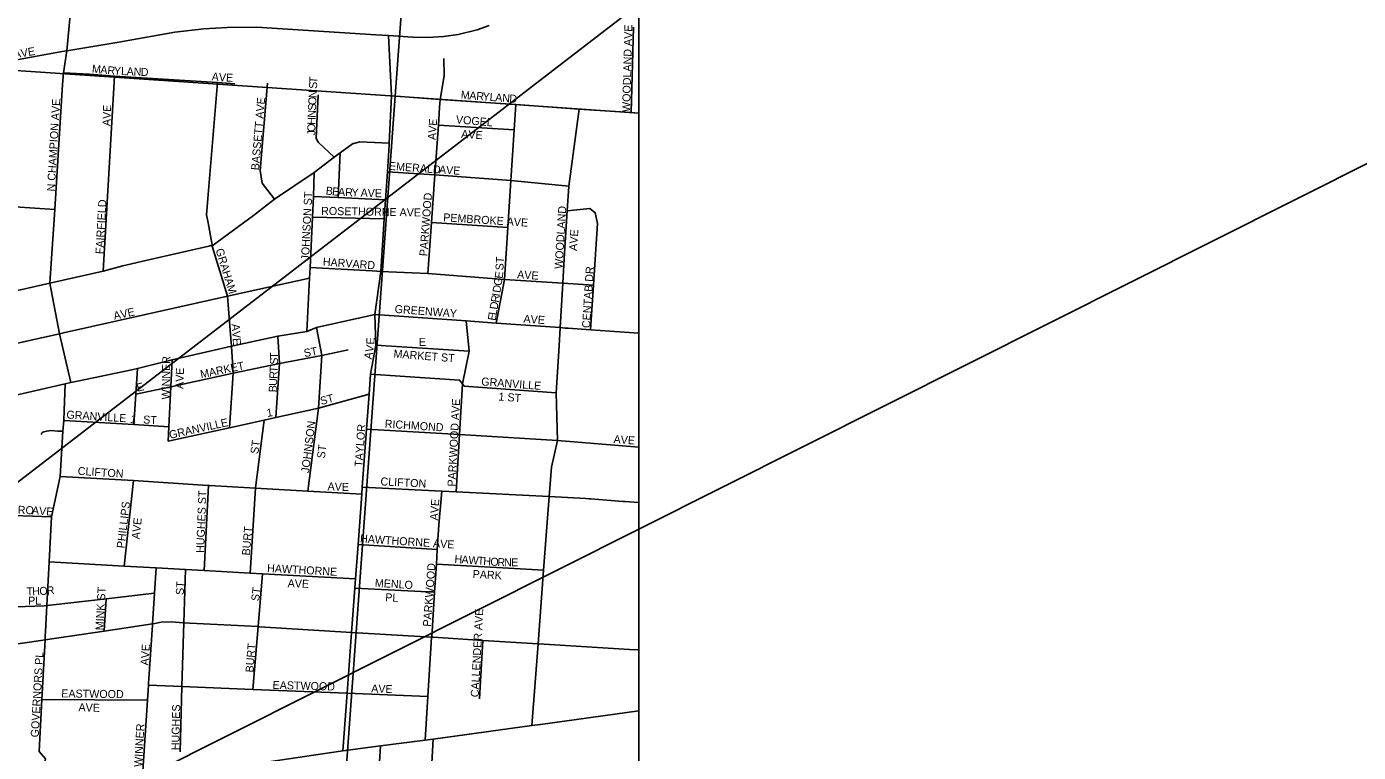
# Model space of a CAD drawing. Extents: x 0 to 34, y -6.2 to 22.
# Drawn here: x 8.351 to 9.927, y 18.357 to 19.216 of the extents above; entities that cross this region are included whole.
import ezdxf

# ---------------------------------------------------------------- set-up
doc = ezdxf.new("R2010")
doc.units = 0
for name, color, linetype in [('GM_X_City_Street', 7, 'Continuous'), ('GM_X_City_Street_Text', 7, 'Continuous'), ('GM_X_Corporation', 7, 'Continuous'), ('GM_X_Section', 7, 'Continuous'), ('GM_X_US_Route', 7, 'Continuous'), ('SH_Data', 7, 'Continuous')]:
    doc.layers.add(name, color=color, linetype=linetype)

msp = doc.modelspace()

# ---------------------------------------------------------------- linework, layer by layer
at = {"layer": 'GM_X_City_Street'}
for points in [[(8.3987, 19.1873), (8.4028, 19.2294), (8.4075, 19.274), (8.4161, 19.3091), (8.445, 19.3931), (8.45, 19.4134), (8.4601, 19.4649), (8.4609, 19.4899), (8.4634, 19.5259)], [(8.393, 19.1863), (8.3987, 19.1873), (8.4604, 19.1976), (8.5267, 19.2092), (8.5608, 19.2131), (8.5883, 19.2147), (8.6233, 19.215), (8.7644, 19.2062)], [(8.7644, 19.2062), (8.7794, 19.2052), (8.808, 19.2033), (8.8254, 19.203), (8.8444, 19.204), (8.8618, 19.2063), (8.8842, 19.2119), (8.8987, 19.2171)], [(9.0664, 19.1141), (9.0693, 19.2152)], [(8.7802, 19.0755), (8.7803, 19.0781), (8.7828, 19.1338), (8.7794, 19.2052)], [(8.3252, 19.174), (8.3329, 19.1755), (8.393, 19.1863)], [(8.3937, 19.1473), (8.3946, 19.1613), (8.3987, 19.1873)], [(8.8398, 19.12), (8.8405, 19.1297), (8.8452, 19.1577), (8.8449, 19.1779)], [(8.3946, 19.1613), (8.4251, 19.1594), (8.455, 19.1571), (8.5769, 19.1496), (8.5976, 19.148)], [(8.4418, 18.9263), (8.455, 19.1571)], [(8.5703, 18.9596), (8.566, 18.9837), (8.564, 18.9932), (8.5657, 19.0125), (8.5769, 19.1496)], [(8.3967, 18.7927), (8.3967, 18.793), (8.4034, 18.7947), (8.3902, 18.8525), (8.3787, 18.9123), (8.3844, 18.9996), (8.3937, 19.1473)], [(8.6445, 19.0118), (8.6299, 19.0305), (8.6276, 19.0457), (8.6362, 19.1488)], [(8.7152, 19.0612), (8.6964, 19.0787), (8.6939, 19.0834), (8.6944, 19.1016), (8.6961, 19.1353)], [(8.7828, 19.1338), (8.8405, 19.1297), (8.9301, 19.1235), (9.005, 19.118), (9.0354, 19.1161)], [(8.8258, 18.9239), (8.8301, 18.9842), (8.8341, 19.0405), (8.8384, 19.0994), (8.8398, 19.12)], [(8.9068, 18.865), (8.9166, 18.9168), (8.9205, 18.978), (8.924, 19.0339), (8.928, 19.0936), (8.9301, 19.1235)], [(8.949, 18.389), (8.9564, 18.4856), (8.963, 18.5728), (8.9697, 18.6597), (8.9724, 18.6947), (8.9792, 18.7261), (8.9779, 18.7826), (8.9814, 18.8383), (8.9826, 18.8597), (8.9857, 18.9124), (8.9874, 18.9415), (8.9909, 18.9979), (8.9928, 19.0271), (9.005, 19.118)], [(9.0354, 19.1161), (9.0664, 19.1141), (9.0755, 19.1135)], [(8.8384, 19.0994), (8.928, 19.0936)], [(8.5766, 18.9609), (8.6197, 18.9924), (8.6445, 19.0118), (8.6916, 19.0434), (8.7152, 19.0612), (8.7221, 19.0663), (8.7369, 19.0772), (8.7456, 19.0796), (8.7803, 19.0781)], [(8.7253, 18.3591), (8.7303, 18.4271), (8.7357, 18.4991), (8.7395, 18.5514), (8.7403, 18.5624), (8.7433, 18.6032), (8.7477, 18.6628), (8.7483, 18.6711), (8.7534, 18.7397), (8.7564, 18.7809), (8.7582, 18.8048), (8.7644, 18.8391), (8.7634, 18.8752), (8.7702, 18.9261), (8.7744, 18.9884), (8.7758, 19.011), (8.7782, 19.0441), (8.7802, 19.0755)], [(8.7199, 19.0136), (8.7221, 19.0663)], [(8.6828, 18.8549), (8.6858, 18.9183), (8.6865, 18.931), (8.6895, 18.9903), (8.6905, 19.0149), (8.6916, 19.0434)], [(8.7782, 19.0441), (8.8341, 19.0405), (8.924, 19.0339), (8.9928, 19.0271)], [(8.6905, 19.0149), (8.7199, 19.0136), (8.7758, 19.011)], [(8.3255, 19.0032), (8.3844, 18.9996)], [(9.0183, 18.8571), (9.0219, 18.9101), (9.0268, 18.9829), (9.0241, 18.9955), (9.0178, 19.0006), (8.9909, 18.9979)], [(8.6895, 18.9903), (8.7744, 18.9884)], [(8.8301, 18.9842), (8.9205, 18.978)], [(8.1258, 18.856), (8.1279, 18.8565), (8.1515, 18.8584), (8.2503, 18.8836), (8.2811, 18.8897), (8.314, 18.8978), (8.3787, 18.9123), (8.4418, 18.9263), (8.4649, 18.9326), (8.4972, 18.9401), (8.5668, 18.9562), (8.5708, 18.9571), (8.5717, 18.9573), (8.5766, 18.9609)], [(8.5933, 18.8417), (8.5887, 18.8968), (8.5709, 18.9562), (8.5708, 18.9571), (8.5706, 18.9581), (8.5703, 18.9596)], [(8.6865, 18.931), (8.7599, 18.9268), (8.7654, 18.9264)], [(8.3949, 18.8535), (8.5887, 18.8968), (8.6858, 18.9183)], [(8.7654, 18.9264), (8.7702, 18.9261), (8.8258, 18.9239), (8.9166, 18.9168), (8.9857, 18.9124), (9.0219, 18.9101)], [(8.4115, 18.7964), (8.4757, 18.8099), (8.4822, 18.8114), (8.5232, 18.8217), (8.5937, 18.8376), (8.5955, 18.838), (8.6484, 18.8497), (8.6828, 18.8549), (8.6943, 18.8599), (8.7634, 18.8752)], [(8.7634, 18.8752), (8.8712, 18.8676), (8.9068, 18.865), (8.9826, 18.8597), (8.9884, 18.8592)], [(8.8594, 18.6654), (8.8633, 18.7331), (8.8669, 18.7933), (8.8748, 18.8317), (8.8712, 18.8676)], [(8.1235, 18.7929), (8.2941, 18.8311), (8.3902, 18.8525), (8.3949, 18.8535)], [(8.6461, 18.7535), (8.6505, 18.8172), (8.6484, 18.8497)], [(8.6839, 18.6663), (8.6966, 18.7645), (8.7003, 18.8267), (8.6943, 18.8599)], [(8.9884, 18.8592), (8.9921, 18.859), (9.0183, 18.8571), (9.0755, 18.8531)], [(8.5914, 18.7413), (8.5954, 18.8056), (8.5937, 18.8376), (8.5935, 18.8386), (8.5933, 18.8417)], [(8.7644, 18.8391), (8.8748, 18.8317)], [(8.4803, 18.781), (8.5217, 18.7897), (8.5954, 18.8056), (8.6505, 18.8172), (8.7003, 18.8267)], [(8.5196, 18.7422), (8.5217, 18.7897), (8.5232, 18.8217)], [(8.7003, 18.8267), (8.7316, 18.8333)], [(8.4781, 18.745), (8.4803, 18.781), (8.4822, 18.8114)], [(8.7582, 18.8048), (8.8635, 18.7976), (8.8669, 18.7933), (8.869, 18.7906), (8.9779, 18.7826)], [(8.3281, 18.7775), (8.3967, 18.793), (8.4034, 18.7947), (8.4115, 18.7964)], [(8.373, 18.4917), (8.3732, 18.4952), (8.3734, 18.5003), (8.3751, 18.5308), (8.3778, 18.5824), (8.3806, 18.6359), (8.3909, 18.6836), (8.3938, 18.737), (8.395, 18.7499), (8.3957, 18.7615), (8.3967, 18.7927)], [(8.5187, 18.7253), (8.5551, 18.7333), (8.5914, 18.7413), (8.6322, 18.7503), (8.6461, 18.7535), (8.6966, 18.7645), (8.7564, 18.7809)], [(8.395, 18.7499), (8.4781, 18.745), (8.5196, 18.7422)], [(8.5187, 18.7253), (8.5196, 18.7422)], [(8.6219, 18.6701), (8.6322, 18.7503)], [(8.7534, 18.7397), (8.8633, 18.7331), (8.9792, 18.7261), (9.0755, 18.7184)], [(8.3683, 18.7333), (8.3697, 18.7355), (8.3715, 18.7365), (8.375, 18.7373), (8.3798, 18.7379), (8.3881, 18.7372), (8.3938, 18.737)], [(8.3909, 18.6836), (8.4775, 18.6787), (8.5654, 18.673), (8.5663, 18.673), (8.5676, 18.6729)], [(8.4665, 18.5775), (8.4775, 18.6787)], [(8.5611, 18.5723), (8.5663, 18.673)], [(8.5676, 18.6729), (8.6218, 18.6698), (8.6839, 18.6663), (8.7477, 18.6628)], [(8.6156, 18.5693), (8.6218, 18.6698), (8.6219, 18.6701)], [(8.7483, 18.6711), (8.8424, 18.6663), (8.8594, 18.6654), (8.9697, 18.6597), (9.013, 18.6575), (9.0169, 18.6572)], [(8.8305, 18.4935), (8.8339, 18.5468), (8.836, 18.5797), (8.8371, 18.5973), (8.8389, 18.6263), (8.8424, 18.6663)], [(9.0169, 18.6572), (9.019, 18.657), (9.0566, 18.6541)], [(9.0566, 18.6541), (9.0589, 18.6539), (9.0755, 18.6526)], [(8.3123, 18.6381), (8.3806, 18.6359)], [(8.7433, 18.6032), (8.8371, 18.5973)], [(8.3778, 18.5824), (8.4665, 18.5775), (8.5043, 18.5754), (8.5392, 18.5735), (8.5611, 18.5723), (8.6156, 18.5693), (8.6303, 18.5685), (8.7403, 18.5624)], [(8.5004, 18.5151), (8.5024, 18.5454), (8.5043, 18.5754)], [(8.5327, 18.3578), (8.535, 18.435), (8.5373, 18.5105), (8.5392, 18.5735)], [(8.6189, 18.4316), (8.6251, 18.5059), (8.6303, 18.5685)], [(8.836, 18.5797), (8.9142, 18.5755), (8.9142, 18.5755)], [(8.9142, 18.5755), (8.963, 18.5728)], [(8.7395, 18.5514), (8.8339, 18.5468)], [(8.3789, 18.5312), (8.4453, 18.5388), (8.5024, 18.5454)], [(8.4428, 18.5007), (8.4453, 18.5388)], [(8.3272, 18.5291), (8.3723, 18.5305), (8.3751, 18.5308), (8.3785, 18.5312), (8.3789, 18.5312)], [(8.3679, 18.4896), (8.3729, 18.4904), (8.4428, 18.5007), (8.5, 18.5091), (8.5007, 18.5092), (8.5102, 18.511), (8.5223, 18.5117), (8.5373, 18.5105), (8.5443, 18.5099), (8.6251, 18.5059), (8.6269, 18.5058), (8.7357, 18.4991), (8.8304, 18.4934), (8.8321, 18.4933), (8.8911, 18.4896), (8.9564, 18.4856), (8.9636, 18.4852), (8.9636, 18.4852)], [(8.4958, 18.4443), (8.4999, 18.5075), (8.5, 18.5091), (8.5004, 18.5151)], [(7.5629, 18.3764), (7.5767, 18.3783), (7.5847, 18.3794), (7.591, 18.3803), (7.5943, 18.3809), (7.6298, 18.3876), (7.6729, 18.3918), (7.749, 18.402), (7.8007, 18.4086), (7.8437, 18.4145), (7.8764, 18.4203), (7.9145, 18.4262), (7.9808, 18.4348), (8.0275, 18.4418), (8.0448, 18.4457), (8.1038, 18.452), (8.1664, 18.4588), (8.2206, 18.4671), (8.289, 18.478), (8.3678, 18.4896), (8.3679, 18.4896)], [(8.3631, 18.3042), (8.3734, 18.3494), (8.3659, 18.3582), (8.3692, 18.4197), (8.3729, 18.4904), (8.373, 18.4917)], [(8.8226, 18.3715), (8.826, 18.4232), (8.8304, 18.4934), (8.8305, 18.4935)], [(8.8869, 18.4203), (8.8911, 18.4896)], [(8.9636, 18.4852), (9.0711, 18.4785), (9.0755, 18.4788)], [(8.4879, 18.3231), (8.4941, 18.4189), (8.4953, 18.4367), (8.4955, 18.4396), (8.4958, 18.4443)], [(8.4953, 18.4367), (8.535, 18.435), (8.6189, 18.4316), (8.7303, 18.4271), (8.826, 18.4232)], [(8.3692, 18.4197), (8.4941, 18.4189)], [(8.7608, 18.2175), (8.7699, 18.3648)], [(8.8262, 18.1321), (8.8232, 18.2118), (8.8321, 18.3727)]]:
    msp.add_lwpolyline(points, dxfattribs=at)
at = {"layer": 'GM_X_Corporation'}
msp.add_lwpolyline([(5.4833, 14.3902), (9.0755, 14.3902), (9.0755, 21.1902), (4.181, 21.1902)], dxfattribs=at)
at = {"layer": 'GM_X_Section'}
for p, q in [((9.0755, 19.1136), (9.0755, 19.6173)), ((9.0755, 18.117), (9.0755, 19.1136))]:
    msp.add_line(p, q, dxfattribs=at)
for points in [[(8.8238, 19.6326), (8.7873, 19.1335), (8.2681, 19.1685), (7.7478, 19.2036), (7.7816, 19.6963)], [(8.2681, 19.1685), (8.7873, 19.1335), (8.7151, 18.1417), (8.198, 18.176)]]:
    msp.add_lwpolyline(points, close=True, dxfattribs=at)
for points in [[(9.0755, 19.6173), (8.9158, 19.6288), (8.8238, 19.6326), (8.7873, 19.1335), (9.0755, 19.1136)], [(9.0755, 19.1136), (8.7873, 19.1335), (8.7151, 18.1417), (9.0755, 18.117)]]:
    msp.add_lwpolyline(points, dxfattribs=at)
at = {"layer": 'GM_X_US_Route'}
for points in [[(8.9591, 18.3903), (9.0755, 18.4061)], [(8.7253, 18.3591), (8.7699, 18.3648), (8.8226, 18.3715), (8.8321, 18.3727), (8.949, 18.389), (8.959, 18.3903), (8.9591, 18.3903)], [(7.7702, 18.2134), (7.8087, 18.22), (7.8159, 18.2211), (7.8223, 18.2222), (7.8858, 18.2297), (7.9034, 18.2324), (7.9636, 18.2412), (8.0195, 18.2496), (8.0627, 18.2556), (8.0929, 18.2603), (8.1544, 18.2697), (8.1656, 18.2711), (8.2163, 18.2789), (8.2815, 18.2885), (8.3569, 18.2998), (8.3631, 18.3042), (8.4344, 18.315), (8.4363, 18.3152), (8.4879, 18.3231), (8.5004, 18.325), (8.5808, 18.3373), (8.6479, 18.3474), (8.7253, 18.3591)]]:
    msp.add_lwpolyline(points, dxfattribs=at)
at = {"layer": 'SH_Data'}
for points in [[(9.0755, 21.1902), (9.0755, 14.3902), (2.2755, 14.3902), (2.2755, 21.1902)], [(10.0459, 19.9888), (6.7517, 17.4551), (10.0459, 19.1081)]]:
    msp.add_lwpolyline(points, close=True, dxfattribs=at)

# ---------------------------------------------------------------- texts
at = {"layer": 'GM_X_City_Street_Text'}
for s, rotation, p in [('WOODLAND AVE', 88.4915, (9.0653, 19.1147)), ('AVE', 10.1268, (8.3368, 19.178)), ('M', 354.6736, (8.4281, 19.1614)), ('A', 354.6809, (8.438, 19.1605)), ('R', 355.0082, (8.4464, 19.1597)), ('Y', 357.0541, (8.4542, 19.159)), ('L', 357.643, (8.4627, 19.1586)), ('A', 357.6509, (8.4693, 19.1583)), ('N', 357.6509, (8.4776, 19.158)), ('D', 357.6509, (8.486, 19.1576)), ('A', 354.4612, (8.5698, 19.1522)), ('V', 356.784, (8.5785, 19.1514)), ('E', 357.126, (8.5869, 19.1509)), ('S', 87.349, (8.6947, 19.142)), ('T', 87.3775, (8.695, 19.1486)), ('N', 87.3548, (8.6942, 19.1311)), ('M', 355.6795, (8.8647, 19.1306)), ('A', 355.6683, (8.8747, 19.1298)), ('R', 355.6637, (8.883, 19.1292)), ('Y', 355.6691, (8.8905, 19.1286)), ('L', 355.6711, (8.8988, 19.128)), ('A', 355.6691, (8.9054, 19.1275)), ('N', 355.6691, (8.9137, 19.1268)), ('D', 355.9615, (8.9221, 19.1262)), ('N CHAMPION AVE', 86.6615, (8.3845, 19.0206)), ('AVE', 88.0261, (8.4503, 19.098)), ('BASSETT AVE', 85.0816, (8.6261, 19.0456)), ('S', 87.349, (8.6935, 19.1162)), ('O', 87.3582, (8.6938, 19.1228)), ('H', 88.1418, (8.6928, 19.0995)), ('N', 87.3984, (8.6931, 19.1078)), ('AVE', 86.0574, (8.8353, 19.0814)), ('VOGEL', 355.1336, (8.8589, 19.1014)), ('O', 89.7814, (8.6928, 19.0913)), ('J', 89.9563, (8.6928, 19.0871)), ('AVE', 356.0569, (8.8652, 19.0843)), ('EMERALD', 355.731, (8.7797, 19.0464)), ('AVE', 356.0569, (8.8389, 19.0422)), ('B', 353.7698, (8.7048, 19.0172)), ('E', 354.3398, (8.7123, 19.0164)), ('A', 357.2457, (8.7195, 19.0157)), ('R', 358.1169, (8.728, 19.0153)), ('Y', 358.1238, (8.7355, 19.015)), ('A', 358.12, (8.7463, 19.0147)), ('V', 358.12, (8.7546, 19.0144)), ('E', 358.1145, (8.763, 19.0141)), ('FAIRFIELD', 86.7772, (8.442, 18.9464)), ('JOHNSON ST', 87.2424, (8.6853, 18.9389)), ('PARKWOOD', 85.7104, (8.8253, 18.9439)), ('ROSETHORNE AVE', 359.0765, (8.6996, 18.9931)), ('PEMBROKE AVE', 356.2915, (8.8439, 18.9856)), ('WOODLAND', 86.51, (8.9853, 18.9289)), ('AVE', 86.0569, (9.0024, 18.9503)), ('GRAHAM', 286.9636, (8.5746, 18.9518)), ('HARVARD', 355.8577, (8.7014, 18.9331)), ('ST', 86.4254, (8.9153, 18.9272)), ('CENTAB DR', 86.3314, (9.0178, 18.8589)), ('G', 80.9103, (8.913, 18.9086)), ('E', 83.0243, (8.9144, 18.9172)), ('AVE', 356.0569, (8.9314, 18.9181)), ('R', 80.5646, (8.9097, 18.8888)), ('I', 80.5714, (8.9109, 18.8962)), ('D', 80.5592, (8.9116, 18.9003)), ('AVE', 12.0958, (8.455, 18.8689)), ('GREENWAY', 355.6563, (8.7864, 18.8772)), ('D', 80.5377, (8.9083, 18.8806)), ('E', 80.5601, (8.9061, 18.8674)), ('L', 80.5584, (8.9072, 18.874)), ('AVE', 356.0569, (8.9389, 18.8656)), ('AVE', 273.8117, (8.5938, 18.8639)), ('ST', 10.6122, (8.6801, 18.8247)), ('V', 80.5919, (8.7611, 18.83)), ('E', 88.0963, (8.7626, 18.8396)), ('E', 0, (8.8154, 18.8381)), ('WINNER', 88.98, (8.5203, 18.7746)), ('MARKET', 11.632, (8.5576, 18.7997)), ('S', 89.1027, (8.6485, 18.8158)), ('T', 89.9457, (8.6486, 18.8227)), ('A', 79.3844, (8.7595, 18.8216)), ('MARKET ST', 355.6037, (8.7851, 18.8243)), ('V', 87.8579, (8.5368, 18.7954)), ('E', 87.8142, (8.5371, 18.8037)), ('R', 87.2372, (8.6477, 18.7989)), ('T', 87.2399, (8.6481, 18.8063)), ('E', 14.0298, (8.4825, 18.7838)), ('A', 88.3384, (8.5366, 18.787)), ('B', 87.2309, (8.647, 18.783)), ('U', 87.2232, (8.6473, 18.7905)), ('GRANVILLE', 355.6565, (8.8889, 18.7914)), ('ST', 14.9378, (8.6999, 18.768)), ('PARKWOOD AVE', 86.9352, (8.8586, 18.6714)), ('1 ST', 355.7579, (8.9093, 18.7735)), ('GRANVILLE', 356.3777, (8.398, 18.7522)), ('1', 350.5377, (8.4732, 18.7472)), ('ST', 356.4262, (8.4888, 18.7464)), ('1', 9.9984, (8.636, 18.7539)), ('GRANVILLE', 12.4488, (8.5209, 18.728)), ('JOHNSON', 82.7636, (8.6853, 18.6873)), ('TAYLOR', 85.9166, (8.7486, 18.6947)), ('RICHMOND', 356.238, (8.7747, 18.7414)), ('ST', 82.8649, (8.6253, 18.7098)), ('AVE', 356.0569, (9.0455, 18.7231)), ('ST', 82.8783, (8.704, 18.7045)), ('CLIFTON', 356.1198, (8.4114, 18.6856)), ('AVE', 358.0186, (8.7071, 18.6672)), ('CLIFTON', 357.087, (8.7697, 18.6731)), ('HUGHES ST', 87.7379, (8.5611, 18.593)), ('METRO', 357.664, (8.3138, 18.6406)), ('AVE', 355.9088, (8.3572, 18.6389)), ('PHILLIPS', 83.2336, (8.467, 18.5982)), ('AVE', 86.0569, (8.8378, 18.6314)), ('AVE', 84.0895, (8.4848, 18.609)), ('BURT', 85.3674, (8.6153, 18.5898)), ('HAWTHORNE AVE', 356.2485, (8.7455, 18.6056)), ('H', 355.8661, (8.8572, 18.5814)), ('A', 355.894, (8.8655, 18.5808)), ('W', 355.8605, (8.8738, 18.5802)), ('T', 355.8716, (8.8846, 18.5794)), ('H', 355.8832, (8.8913, 18.5789)), ('O', 355.8879, (8.8996, 18.5783)), ('R', 356.8676, (8.9081, 18.5777)), ('N', 359.5311, (8.9161, 18.5773)), ('E', 359.9956, (8.9245, 18.5772)), ('HAWTHORNE', 356.7837, (8.6355, 18.5706)), ('PARKWOOD', 85.7131, (8.8295, 18.5056)), ('PARK', 356.9075, (8.8788, 18.5635)), ('T', 1.8522, (8.3513, 18.5428)), ('H', 1.8582, (8.3579, 18.543)), ('O', 1.8363, (8.3663, 18.5433)), ('R', 6.7447, (8.3755, 18.5436)), ('MINK ST', 86.9888, (8.442, 18.5014)), ('ST', 86.4262, (8.537, 18.5431)), ('ST', 82.8649, (8.6261, 18.5357)), ('AVE', 358.0186, (8.6599, 18.5526)), ('MENLO', 356.4939, (8.763, 18.5531)), ('PL', 0, (8.3529, 18.5319)), ('PL', 356.4254, (8.7753, 18.5361)), ('CALLENDER AVE', 87.0131, (8.8861, 18.4222)), ('GOVERNORS PL', 86.7292, (8.3653, 18.3747)), ('AVE', 86.0569, (8.4953, 18.4597)), ('BURT', 85.361, (8.6195, 18.4514)), ('EASTWOOD', 358.532, (8.6421, 18.4322)), ('EASTWOOD', 359.2659, (8.3921, 18.4222)), ('AVE', 358.0261, (8.7588, 18.4281)), ('AVE', 358.0261, (8.4124, 18.4059)), ('HUGHES', 88.9775, (8.5319, 18.3596)), ('WINNER', 86.9313, (8.4878, 18.3397))]:
    msp.add_text(s, height=0.00947, rotation=rotation, dxfattribs=at).set_placement(p)

doc.saveas('drawing.dxf')
